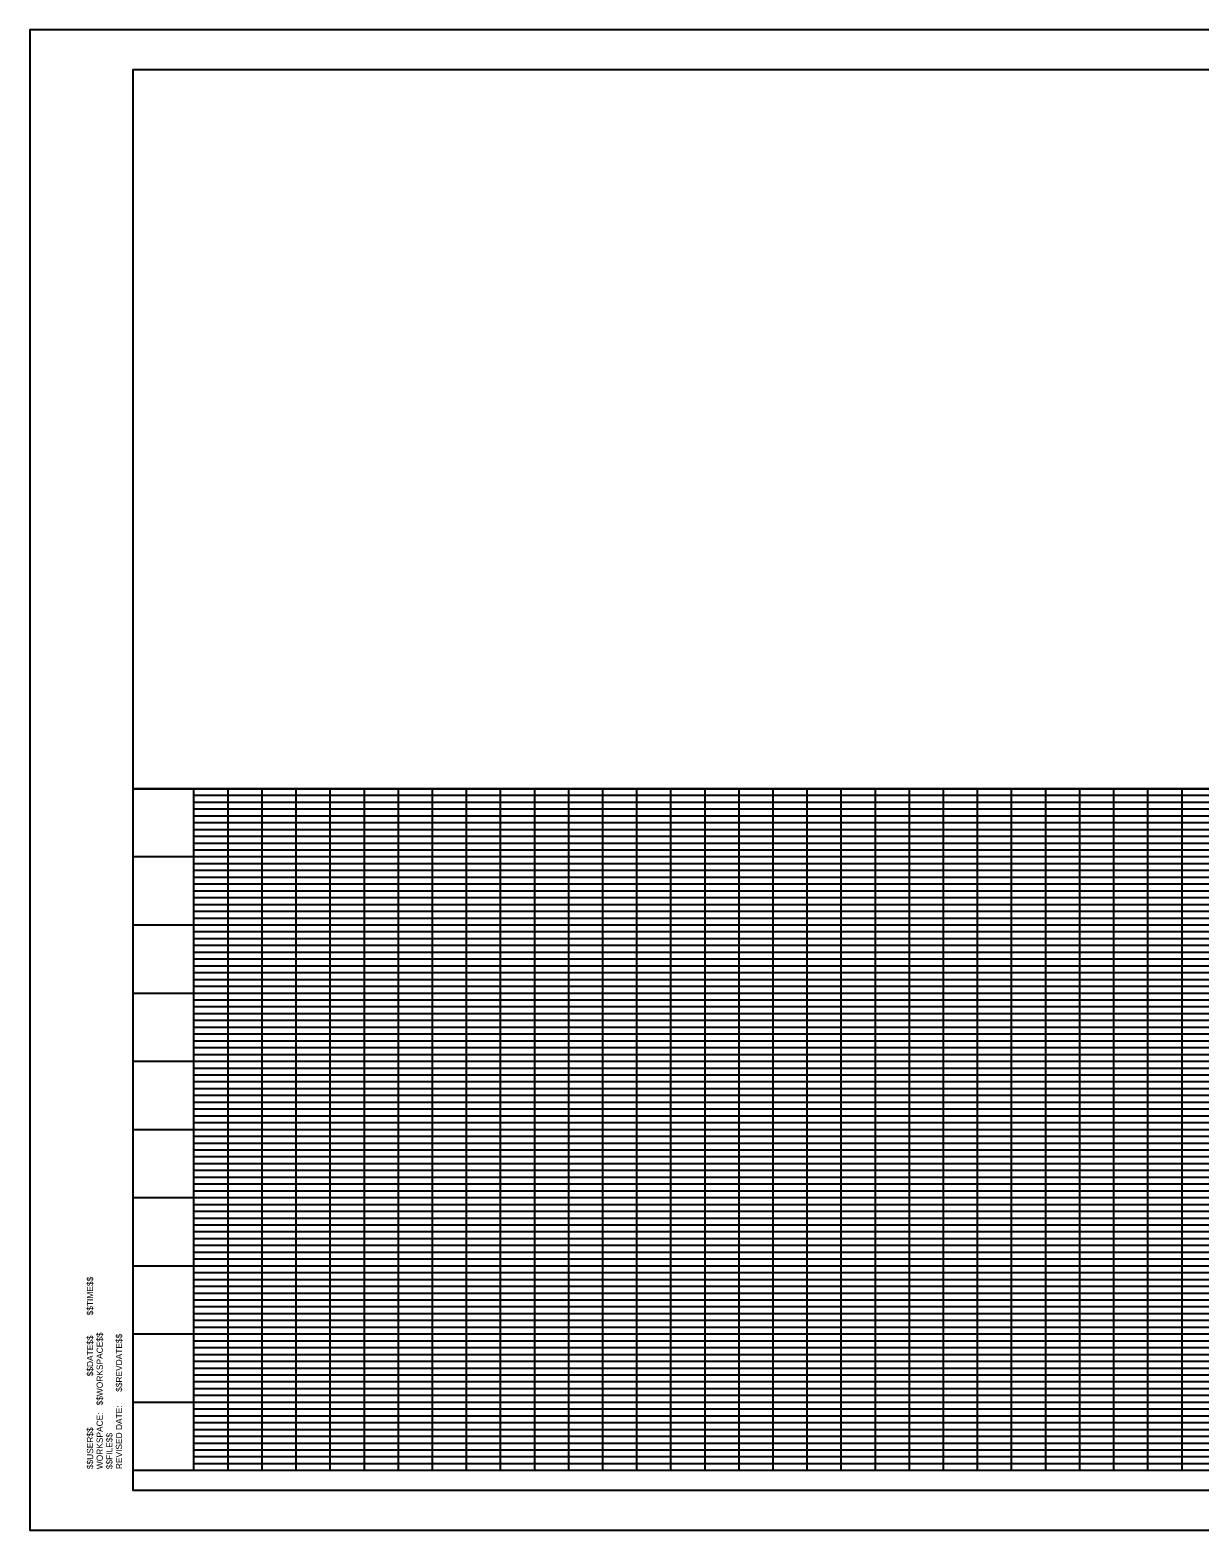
# Model space of a CAD drawing. Extents: x 0 to 1228740, y 0 to 152440.
# Drawn here: x 0 to 17.16, y 0 to 22 of the extents above; entities that cross this region are included whole.
import ezdxf

# ---------------------------------------------------------------- set-up
doc = ezdxf.new("R2010")
doc.units = 0
for name, color, linetype in [('G-TBLK', 7, 'Continuous'), ('R_Border', 7, 'Continuous'), ('R_Grid', 7, 'Continuous'), ('R_No Plot', 7, 'Continuous')]:
    doc.layers.add(name, color=color, linetype=linetype)

msp = doc.modelspace()

# ---------------------------------------------------------------- linework, layer by layer
at = {"layer": 'R_Border'}
for p, q in [((1.516, 21.423), (33.423, 21.423)), ((1.516, 0.577), (1.516, 21.423)), ((33.423, 0.577), (1.516, 0.577))]:
    msp.add_line(p, q, dxfattribs=at)
msp.add_lwpolyline([(34, 22), (0, 22), (0, 0), (34, 0)], close=True, dxfattribs=at)
at = {"layer": 'R_Grid'}
for p, q in [((33.423, 10.871), (1.516, 10.871)), ((2.407, 0.871), (2.407, 10.871)), ((2.907, 0.871), (2.907, 10.871)), ((3.407, 0.871), (3.407, 10.871)), ((3.907, 0.871), (3.907, 10.871)), ((4.407, 0.871), (4.407, 10.871)), ((4.907, 0.871), (4.907, 10.871)), ((5.407, 0.871), (5.407, 10.871)), ((5.907, 0.871), (5.907, 10.871)), ((6.407, 0.871), (6.407, 10.871)), ((6.907, 0.871), (6.907, 10.871)), ((7.407, 0.871), (7.407, 10.871)), ((7.907, 0.871), (7.907, 10.871)), ((8.407, 0.871), (8.407, 10.871)), ((8.907, 0.871), (8.907, 10.871)), ((9.407, 0.871), (9.407, 10.871)), ((9.907, 0.871), (9.907, 10.871)), ((10.407, 0.871), (10.407, 10.871)), ((10.907, 0.871), (10.907, 10.871)), ((11.407, 0.871), (11.407, 10.871)), ((11.907, 0.871), (11.907, 10.871)), ((12.407, 0.871), (12.407, 10.871)), ((12.907, 0.871), (12.907, 10.871)), ((13.407, 0.871), (13.407, 10.871)), ((13.907, 0.871), (13.907, 10.871)), ((14.407, 0.871), (14.407, 10.871)), ((14.907, 0.871), (14.907, 10.871)), ((15.407, 0.871), (15.407, 10.871)), ((15.907, 0.871), (15.907, 10.871)), ((16.407, 0.871), (16.407, 10.871)), ((16.907, 0.871), (16.907, 10.871)), ((32.407, 10.771), (2.407, 10.771)), ((32.407, 10.671), (2.407, 10.671)), ((32.407, 10.571), (2.407, 10.571)), ((32.407, 10.471), (2.407, 10.471)), ((32.407, 10.371), (2.407, 10.371)), ((32.407, 10.271), (2.407, 10.271)), ((32.407, 10.171), (2.407, 10.171)), ((32.407, 10.071), (2.407, 10.071)), ((32.407, 9.971), (2.407, 9.971)), ((33.423, 9.871), (1.516, 9.871)), ((32.407, 9.771), (2.407, 9.771)), ((32.407, 9.671), (2.407, 9.671)), ((32.407, 9.571), (2.407, 9.571)), ((32.407, 9.471), (2.407, 9.471)), ((32.407, 9.371), (2.407, 9.371)), ((32.407, 9.271), (2.407, 9.271)), ((32.407, 9.171), (2.407, 9.171)), ((32.407, 9.071), (2.407, 9.071)), ((33.423, 8.871), (1.516, 8.871)), ((32.407, 8.971), (2.407, 8.971)), ((32.407, 8.771), (2.407, 8.771)), ((32.407, 8.671), (2.407, 8.671)), ((32.407, 8.571), (2.407, 8.571)), ((32.407, 8.471), (2.407, 8.471)), ((32.407, 8.371), (2.407, 8.371)), ((32.407, 8.271), (2.407, 8.271)), ((32.407, 8.171), (2.407, 8.171)), ((32.407, 8.071), (2.407, 8.071)), ((32.407, 7.971), (2.407, 7.971)), ((33.423, 7.871), (1.516, 7.871)), ((32.407, 7.771), (2.407, 7.771)), ((32.407, 7.671), (2.407, 7.671)), ((32.407, 7.571), (2.407, 7.571)), ((32.407, 7.471), (2.407, 7.471)), ((32.407, 7.371), (2.407, 7.371)), ((32.407, 7.271), (2.407, 7.271)), ((32.407, 7.171), (2.407, 7.171)), ((32.407, 7.071), (2.407, 7.071)), ((33.423, 6.871), (1.516, 6.871)), ((32.407, 6.971), (2.407, 6.971)), ((32.407, 6.771), (2.407, 6.771)), ((32.407, 6.671), (2.407, 6.671)), ((32.407, 6.571), (2.407, 6.571)), ((32.407, 6.471), (2.407, 6.471)), ((32.407, 6.371), (2.407, 6.371)), ((32.407, 6.271), (2.407, 6.271)), ((32.407, 6.171), (2.407, 6.171)), ((32.407, 6.071), (2.407, 6.071)), ((32.407, 5.971), (2.407, 5.971)), ((33.423, 5.871), (1.516, 5.871)), ((32.407, 5.771), (2.407, 5.771)), ((32.407, 5.671), (2.407, 5.671)), ((32.407, 5.571), (2.407, 5.571)), ((32.407, 5.471), (2.407, 5.471)), ((32.407, 5.371), (2.407, 5.371)), ((32.407, 5.271), (2.407, 5.271)), ((32.407, 5.171), (2.407, 5.171)), ((32.407, 5.071), (2.407, 5.071)), ((33.423, 4.871), (1.516, 4.871)), ((32.407, 4.971), (2.407, 4.971)), ((32.407, 4.771), (2.407, 4.771)), ((32.407, 4.671), (2.407, 4.671)), ((32.407, 4.571), (2.407, 4.571)), ((32.407, 4.471), (2.407, 4.471)), ((32.407, 4.371), (2.407, 4.371)), ((32.407, 4.271), (2.407, 4.271)), ((32.407, 4.171), (2.407, 4.171)), ((32.407, 4.071), (2.407, 4.071)), ((32.407, 3.971), (2.407, 3.971)), ((33.423, 3.871), (1.516, 3.871)), ((32.407, 3.771), (2.407, 3.771)), ((32.407, 3.671), (2.407, 3.671)), ((32.407, 3.571), (2.407, 3.571)), ((32.407, 3.471), (2.407, 3.471)), ((32.407, 3.371), (2.407, 3.371)), ((32.407, 3.271), (2.407, 3.271)), ((32.407, 3.171), (2.407, 3.171)), ((33.423, 2.871), (1.516, 2.871)), ((32.407, 3.071), (2.407, 3.071)), ((32.407, 2.971), (2.407, 2.971)), ((32.407, 2.771), (2.407, 2.771)), ((32.407, 2.671), (2.407, 2.671)), ((32.407, 2.571), (2.407, 2.571)), ((32.407, 2.471), (2.407, 2.471)), ((32.407, 2.371), (2.407, 2.371)), ((32.407, 2.271), (2.407, 2.271)), ((32.407, 2.171), (2.407, 2.171)), ((32.407, 2.071), (2.407, 2.071)), ((33.423, 1.871), (1.516, 1.871)), ((32.407, 1.971), (2.407, 1.971)), ((32.407, 1.771), (2.407, 1.771)), ((32.407, 1.671), (2.407, 1.671)), ((32.407, 1.571), (2.407, 1.571)), ((32.407, 1.471), (2.407, 1.471)), ((32.407, 1.371), (2.407, 1.371)), ((32.407, 1.271), (2.407, 1.271)), ((32.407, 1.171), (2.407, 1.171)), ((32.407, 1.071), (2.407, 1.071)), ((32.407, 0.971), (2.407, 0.971)), ((33.423, 0.871), (1.516, 0.871))]:
    msp.add_line(p, q, dxfattribs=at)
at = {"layer": 'R_No Plot'}
msp.add_lwpolyline([(33.423, 17.405), (33.423, 10.871), (1.516, 10.871), (1.516, 21.423), (25.197, 21.423), (25.197, 20.435), (28.749, 20.435), (28.749, 20.078), (29.113, 20.078), (29.113, 20.143), (30.667, 20.143)], dxfattribs=at)
msp.add_lwpolyline([(1.516, 10.871), (33.423, 10.871), (33.423, 0.577), (1.516, 0.577)], close=True, dxfattribs=at)

# ---------------------------------------------------------------- texts
at = {"layer": 'G-TBLK'}
for s, p in [('$$TIME$$', (0.927, 3.148)), ('$$WORKSPACE$$', (1.069, 1.827)), ('$$REVDATE$$', (1.352, 2.026)), ('$$DATE$$', (0.927, 2.254)), ('REVISED DATE:', (1.352, 0.893)), ('WORKSPACE:', (1.069, 0.892)), ('$$USER$$', (0.927, 0.892)), ('$$FILE$$', (1.211, 0.892))]:
    msp.add_text(s, height=0.0918, rotation=90, dxfattribs=at).set_placement(p)

doc.saveas('drawing.dxf')
